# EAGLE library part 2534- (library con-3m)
3M (TM) Pak 100 4-Wall Header Source: 3M
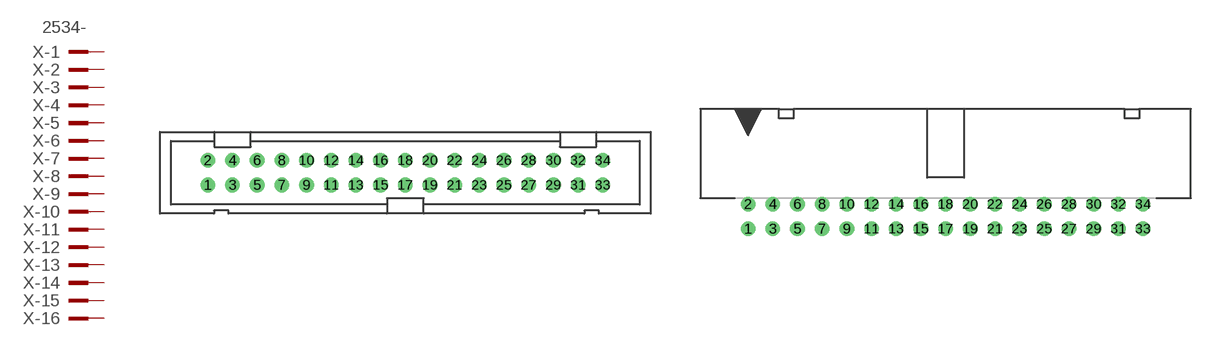
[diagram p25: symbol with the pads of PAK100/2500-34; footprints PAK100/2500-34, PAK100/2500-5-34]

Designator prefix X; gates -1=PINV -2=PIN -3=PIN -4=PIN -5=PIN -6=PIN -7=PIN -8=PIN -9=PIN -10=PIN -11=PIN -12=PIN -13=PIN -14=PIN -15=PIN -16=PIN -17=PIN -18=PIN -19=PIN -20=PIN -21=PIN -22=PIN -23=PIN -24=PIN -25=PIN -26=PIN -27=PIN -28=PIN -29=PIN -30=PIN -31=PIN -32=PIN -33=PIN -34=PIN

## 2534- (OC_FARNELL: unknown; OC_NEWARK: unknown)  [PAK100/2500-34]
1  -1:KL  pas
2  -2:KL  pas
3  -3:KL  pas
4  -4:KL  pas
5  -5:KL  pas
6  -6:KL  pas
7  -7:KL  pas
8  -8:KL  pas
9  -9:KL  pas
10  -10:KL  pas
11  -11:KL  pas
12  -12:KL  pas
13  -13:KL  pas
14  -14:KL  pas
15  -15:KL  pas
16  -16:KL  pas
17  -17:KL  pas
18  -18:KL  pas
19  -19:KL  pas
20  -20:KL  pas
21  -21:KL  pas
22  -22:KL  pas
23  -23:KL  pas
24  -24:KL  pas
25  -25:KL  pas
26  -26:KL  pas
27  -27:KL  pas
28  -28:KL  pas
29  -29:KL  pas
30  -30:KL  pas
31  -31:KL  pas
32  -32:KL  pas
33  -33:KL  pas
34  -34:KL  pas

## 2534-5 (OC_FARNELL: 9838406; OC_NEWARK: unknown)  [PAK100/2500-5-34]
Pads as for PAK100/2500-34

## Footprint PAK100/2500-34 (pad centres in mm)
3M (TM) Pak 100 4-Wall Header Straight Source: 3M
drill 1 pad 1.422 round: 1 -20.32,-1.27; 2 -20.32,1.27; 3 -17.78,-1.27; 4 -17.78,1.27; 5 -15.24,-1.27; 6 -15.24,1.27; 7 -12.7,-1.27; 8 -12.7,1.27; 9 -10.16,-1.27; 10 -10.16,1.27; 11 -7.62,-1.27; 12 -7.62,1.27; 13 -5.08,-1.27; 14 -5.08,1.27; 15 -2.54,-1.27; 16 -2.54,1.27; 17 0,-1.27; 18 0,1.27; 19 2.54,-1.27; 20 2.54,1.27; 21 5.08,-1.27; 22 5.08,1.27; 23 7.62,-1.27; 24 7.62,1.27; 25 10.16,-1.27; 26 10.16,1.27; 27 12.7,-1.27; 28 12.7,1.27; 29 15.24,-1.27; 30 15.24,1.27; 31 17.78,-1.27; 32 17.78,1.27; 33 20.32,-1.27; 34 20.32,1.27

## Footprint PAK100/2500-5-34 (pad centres in mm)
3M (TM) Pak 100 4-Wall Header Right Angle Source: 3M
drill 1 pad 1.422 round: 1 -20.32,-1.27; 2 -20.32,1.27; 3 -17.78,-1.27; 4 -17.78,1.27; 5 -15.24,-1.27; 6 -15.24,1.27; 7 -12.7,-1.27; 8 -12.7,1.27; 9 -10.16,-1.27; 10 -10.16,1.27; 11 -7.62,-1.27; 12 -7.62,1.27; 13 -5.08,-1.27; 14 -5.08,1.27; 15 -2.54,-1.27; 16 -2.54,1.27; 17 0,-1.27; 18 0,1.27; 19 2.54,-1.27; 20 2.54,1.27; 21 5.08,-1.27; 22 5.08,1.27; 23 7.62,-1.27; 24 7.62,1.27; 25 10.16,-1.27; 26 10.16,1.27; 27 12.7,-1.27; 28 12.7,1.27; 29 15.24,-1.27; 30 15.24,1.27; 31 17.78,-1.27; 32 17.78,1.27; 33 20.32,-1.27; 34 20.32,1.27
